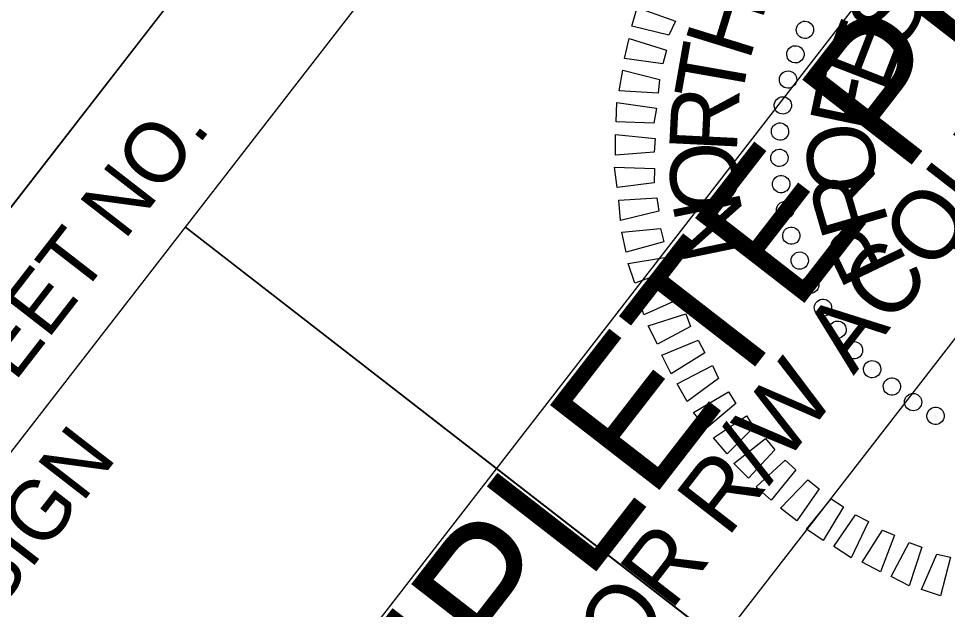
# Model space of a CAD drawing. Extents: x 2013373 to 2015284, y 444589 to 446636.
# Drawn here: x 2014373.4 to 2014450.7, y 446466.6 to 446515.8 of the extents above; entities that cross this region are included whole.
import ezdxf

# ---------------------------------------------------------------- set-up
doc = ezdxf.new("R2010")
doc.units = 0
for name, color, linetype in [('Sheet Plan And Profile CELL', 7, 'Continuous'), ('Sheet Professional Seal CELL', 7, 'Continuous'), ('Sheet Sticker Exception Certification CELL', 7, 'Continuous'), ('Sheet Sticker Incomplete CELL', 7, 'Continuous')]:
    doc.layers.add(name, color=color, linetype=linetype)

msp = doc.modelspace()

# ---------------------------------------------------------------- linework, layer by layer
at = {"layer": 'Sheet Plan And Profile CELL'}
for p, q in [((2014316.128, 446427.001), (2014438.726, 446585.082)), ((2014387.32, 446498.401), (2014476.179, 446429.487))]:
    msp.add_line(p, q, dxfattribs=at)
for points in [[(2014296.333, 446442.352), (2014418.931, 446600.434), (2014438.726, 446585.082), (2014316.128, 446427.001)], [(2014387.32, 446498.401), (2014448.604, 446577.422), (2014537.502, 446508.477), (2014476.219, 446429.457)], [(2014326.006, 446419.34), (2014387.32, 446498.401), (2014476.219, 446429.457), (2014414.904, 446350.396)]]:
    msp.add_lwpolyline(points, close=True, dxfattribs=at)
at = {"layer": 'Sheet Professional Seal CELL'}
for p, q in [((2014438.827, 446514.801), (2014438.827, 446514.801)), ((2014438.014, 446512.774), (2014438.014, 446512.774)), ((2014437.42, 446510.703), (2014437.42, 446510.703)), ((2014437.016, 446508.549), (2014437.016, 446508.549)), ((2014436.76, 446506.343), (2014436.76, 446506.343)), ((2014436.675, 446504.194), (2014436.675, 446504.194)), ((2014436.849, 446501.971), (2014436.849, 446501.971)), ((2014437.155, 446499.836), (2014437.155, 446499.836)), ((2014437.71, 446497.697), (2014437.71, 446497.697)), ((2014438.367, 446495.606), (2014438.367, 446495.606)), ((2014439.295, 446493.621), (2014439.295, 446493.621)), ((2014440.324, 446491.684), (2014440.324, 446491.684)), ((2014441.554, 446489.844), (2014441.554, 446489.844)), ((2014442.938, 446488.201), (2014442.938, 446488.201)), ((2014444.422, 446486.607), (2014444.422, 446486.607)), ((2014446.069, 446485.14), (2014446.069, 446485.14)), ((2014447.838, 446483.831), (2014447.838, 446483.831)), ((2014449.721, 446482.751), (2014449.721, 446482.751))]:
    msp.add_line(p, q, dxfattribs=at)
for points in [[(2014427.548, 446514.373), (2014424.46, 446515.123), (2014424.905, 446516.676), (2014428.077, 446515.545)], [(2014427.03, 446511.991), (2014423.837, 446512.443), (2014424.233, 446514.096), (2014427.348, 446513.136)], [(2014426.66, 446509.557), (2014423.393, 446509.749), (2014423.711, 446511.465), (2014426.769, 446510.675)], [(2014426.3, 446507.052), (2014423.151, 446507.153), (2014423.197, 446508.762), (2014426.5, 446508.289)], [(2014426.321, 446504.631), (2014423.107, 446504.403), (2014423.104, 446506.114), (2014426.389, 446505.781)], [(2014426.32, 446502.101), (2014423.233, 446501.711), (2014423.02, 446503.395), (2014426.349, 446503.281)], [(2014426.692, 446499.725), (2014423.509, 446498.966), (2014423.366, 446500.659), (2014426.55, 446500.847)], [(2014427.121, 446497.178), (2014423.986, 446496.318), (2014423.633, 446497.984), (2014426.838, 446498.282)], [(2014427.703, 446494.828), (2014424.705, 446493.736), (2014424.141, 446495.375), (2014427.35, 446495.924)], [(2014428.364, 446492.417), (2014425.463, 446491.124), (2014424.969, 446492.772), (2014428.143, 446493.601)], [(2014429.328, 446490.151), (2014426.593, 446488.665), (2014425.828, 446490.208), (2014428.945, 446491.207)], [(2014430.532, 446487.951), (2014427.724, 446486.206), (2014426.958, 446487.749), (2014429.969, 446489.021)], [(2014431.658, 446485.813), (2014429.047, 446483.915), (2014428.22, 446485.378), (2014431.165, 446486.891)], [(2014433.095, 446483.749), (2014430.681, 446481.698), (2014429.592, 446482.986), (2014432.51, 446484.709)], [(2014434.593, 446481.765), (2014432.377, 446479.56), (2014431.248, 446480.879), (2014434.008, 446482.725)], [(2014436.363, 446479.886), (2014434.165, 446477.541), (2014432.944, 446478.741), (2014435.568, 446480.819)], [(2014438.106, 446478.218), (2014436.035, 446475.711), (2014434.793, 446476.801), (2014437.219, 446479.032)], [(2014440.051, 446476.646), (2014438.178, 446473.986), (2014436.834, 446475.028), (2014439.103, 446477.382)], [(2014442.057, 446475.154), (2014440.381, 446472.34), (2014438.977, 446473.303), (2014441.048, 446475.81)], [(2014444.137, 446473.92), (2014442.699, 446470.923), (2014441.264, 446471.846), (2014443.067, 446474.497)], [(2014446.31, 446472.805), (2014445.13, 446469.733), (2014443.603, 446470.538), (2014445.296, 446473.211)], [(2014448.574, 446471.808), (2014447.522, 446468.575), (2014446.034, 446469.349), (2014447.53, 446472.175)], [(2014450.961, 446470.969), (2014450.119, 446467.762), (2014448.557, 446468.278), (2014449.825, 446471.218)]]:
    msp.add_lwpolyline(points, close=True, dxfattribs=at)
for centre, major_axis in [((2014438.859, 446514.817), (-0.659, 0.29)), ((2014438.064, 446512.779), (-0.682, 0.232)), ((2014437.45, 446510.679), (-0.699, 0.172)), ((2014437.021, 446508.533), (-0.712, 0.11)), ((2014436.782, 446506.359), (-0.718, 0.048)), ((2014436.732, 446504.171), (-0.72, -0.015)), ((2014436.874, 446501.988), (-0.716, -0.078)), ((2014437.205, 446499.825), (-0.706, -0.14)), ((2014437.723, 446497.699), (-0.691, -0.201)), ((2014438.425, 446495.627), (-0.671, -0.26)), ((2014439.304, 446493.624), (-0.646, -0.318)), ((2014440.355, 446491.705), (-0.616, -0.373)), ((2014441.569, 446489.884), (-0.581, -0.425)), ((2014442.938, 446488.177), (-0.542, -0.474)), ((2014444.449, 446486.595), (-0.498, -0.52)), ((2014446.093, 446485.151), (-0.451, -0.561)), ((2014447.857, 446483.856), (-0.4, -0.598)), ((2014449.726, 446482.72), (-0.347, -0.631))]:
    msp.add_ellipse(centre, major_axis=major_axis, ratio=0.999708, dxfattribs=at)
at = {"layer": 'Sheet Sticker Incomplete CELL'}
msp.add_lwpolyline([(2014386.726, 446405.848), (2014368.156, 446420.25), (2014458.243, 446536.411), (2014476.813, 446522.009)], close=True, dxfattribs=at)

# ---------------------------------------------------------------- texts
at = {"layer": 'Sheet Plan And Profile CELL'}
for s, p in [('R/W SHEET NO.', (2014358.33, 446466.405)), ('ROADWAY DESIGN', (2014343.663, 446430.197))]:
    msp.add_text(s, height=5.0001, rotation=52.2051, dxfattribs=at).set_placement(p)
at = {"layer": 'Sheet Professional Seal CELL'}
for s, height, rotation, p in [('S', 5.638, 59.46071, (2014446.776, 446512.812)), ('H', 5.638, 72.82458, (2014434.213, 446512.115)), ('E', 5.638, 68.81617, (2014445.491, 446509.443)), ('T', 5.638, 80.02488, (2014433.525, 446508.536)), ('F', 5.638, 78.17214, (2014444.715, 446505.995)), ('R', 5.638, 87.22561, (2014433.18, 446504.501)), ('O', 5.639, 96.88634, (2014445.024, 446501.579)), ('O', 5.638, 94.42685, (2014433.515, 446499.875)), ('R', 5.639, 106.24475, (2014445.888, 446498.695)), ('N', 5.639, 101.6286, (2014434.397, 446496.28)), ('P', 5.639, 115.60399, (2014447.436, 446495.469))]:
    msp.add_text(s, height=height, rotation=rotation, dxfattribs=at).set_placement(p)
at = {"layer": 'Sheet Sticker Exception Certification CELL'}
for s, p in [('DOCUMENT NOT CONSIDERED FINAL', (2014433.141, 446350.965)), ('UNLESS ALL SIGNATURES COMPLETED', (2014437.738, 446340.146))]:
    msp.add_text(s, height=6.12398, rotation=52.2051, dxfattribs=at).set_placement(p)
at = {"layer": 'Sheet Sticker Incomplete CELL'}
for s, height, p in [('INCOMPLETE PLANS', 11.52, (2014382.965, 446420.091)), ('DO NOT USE FOR R/W ACQUISITION', 5.76, (2014390.449, 446418.4))]:
    msp.add_text(s, height=height, rotation=52.2051, dxfattribs=at).set_placement(p)

doc.saveas('drawing.dxf')
